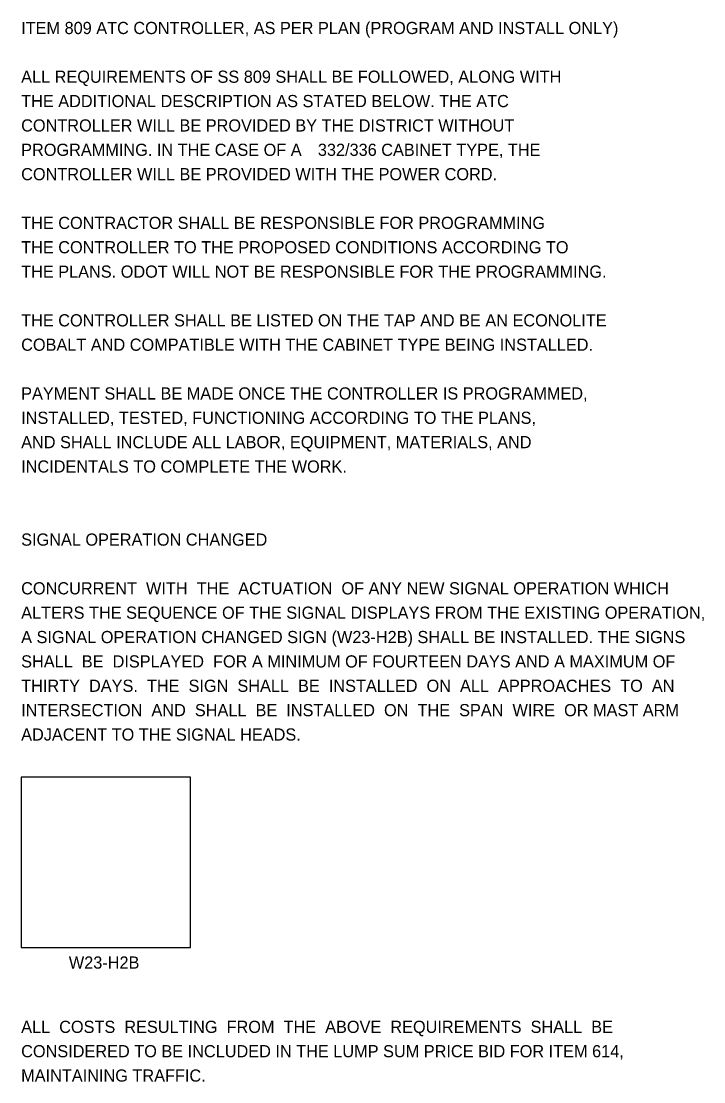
# Model space of a CAD drawing. Extents: x 0 to 44.9, y 0 to 22.
# Drawn here: x 37.05 to 44.9, y 8.74 to 20.93 of the extents above; entities that cross this region are included whole.
import ezdxf

# ---------------------------------------------------------------- set-up
doc = ezdxf.new("R2010")
doc.units = 0
doc.layers.add('SH_Text', color=7, linetype='Continuous')

msp = doc.modelspace()

# ---------------------------------------------------------------- linework, layer by layer
at = {"layer": 'SH_Text'}
msp.add_lwpolyline([(37.052, 10.282), (38.998, 10.282), (38.998, 12.242), (37.052, 12.242)], close=True, dxfattribs=at)

# ---------------------------------------------------------------- texts
for s, p in [('ITEM 809 ATC CONTROLLER, AS PER PLAN (PROGRAM AND INSTALL ONLY)', (37.052, 20.782)), ('ALL REQUIREMENTS OF SS 809 SHALL BE FOLLOWED, ALONG WITH', (37.052, 20.222)), ('THE ADDITIONAL DESCRIPTION AS STATED BELOW. THE ATC ', (37.052, 19.942)), ('CONTROLLER WILL BE PROVIDED BY THE DISTRICT WITHOUT', (37.052, 19.662)), ('PROGRAMMING. IN THE CASE OF A', (37.052, 19.382)), (' 332/336 CABINET TYPE, THE', (40.411, 19.382)), ('CONTROLLER WILL BE PROVIDED WITH THE POWER CORD.', (37.052, 19.102)), ('THE CONTRACTOR SHALL BE RESPONSIBLE FOR PROGRAMMING', (37.052, 18.542)), ('THE CONTROLLER TO THE PROPOSED CONDITIONS ACCORDING TO', (37.052, 18.262)), ('THE PLANS. ODOT WILL NOT BE RESPONSIBLE FOR THE PROGRAMMING.', (37.052, 17.982)), ('THE CONTROLLER SHALL BE LISTED ON THE TAP AND BE AN ECONOLITE', (37.052, 17.422)), ('COBALT AND COMPATIBLE WITH THE CABINET TYPE BEING INSTALLED.', (37.052, 17.142)), ('PAYMENT SHALL BE MADE ONCE THE CONTROLLER IS PROGRAMMED,', (37.052, 16.582)), ('INSTALLED, TESTED, FUNCTIONING ACCORDING TO THE PLANS,', (37.052, 16.302)), ('AND SHALL INCLUDE ALL LABOR, EQUIPMENT, MATERIALS, AND', (37.052, 16.022)), ('INCIDENTALS TO COMPLETE THE WORK.', (37.052, 15.742)), ('SIGNAL OPERATION CHANGED', (37.052, 14.902)), ('CONCURRENT  WITH  THE  ACTUATION  OF ANY NEW SIGNAL OPERATION WHICH', (37.052, 14.342)), ('ALTERS THE SEQUENCE OF THE SIGNAL DISPLAYS FROM THE EXISTING OPERATION,', (37.052, 14.062)), ('A SIGNAL OPERATION CHANGED SIGN (W23-H2B) SHALL BE INSTALLED. THE SIGNS', (37.052, 13.782)), ('SHALL  BE  DISPLAYED  FOR A MINIMUM OF FOURTEEN DAYS AND A MAXIMUM OF', (37.052, 13.502)), ('THIRTY  DAYS.  THE  SIGN  SHALL  BE  INSTALLED  ON  ALL  APPROACHES  TO  AN', (37.052, 13.222)), ('INTERSECTION  AND  SHALL  BE  INSTALLED  ON  THE  SPAN  WIRE  OR MAST ARM', (37.052, 12.942)), ('ADJACENT TO THE SIGNAL HEADS.', (37.052, 12.662)), ('W23-H2B', (37.6, 10.041)), ('ALL  COSTS  RESULTING  FROM  THE  ABOVE  REQUIREMENTS  SHALL  BE', (37.052, 9.302)), ('CONSIDERED TO BE INCLUDED IN THE LUMP SUM PRICE BID FOR ITEM 614,', (37.052, 9.022)), ('MAINTAINING TRAFFIC.', (37.052, 8.742))]:
    msp.add_text(s, height=0.14, dxfattribs=at).set_placement(p)

doc.saveas('drawing.dxf')
